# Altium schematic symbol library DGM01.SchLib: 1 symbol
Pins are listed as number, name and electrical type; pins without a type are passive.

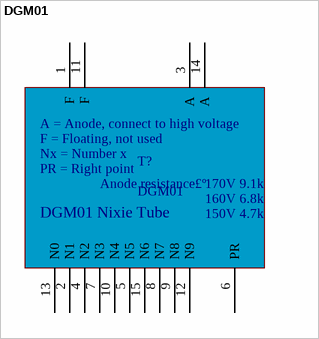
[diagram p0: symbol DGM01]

## DGM01
designator T?
inixielab.com
footprint DGM01 (DGM01 socket)
pins: 1 F, 2 N1, 3 A, 4 N2, 5 N5, 6 PR, 7 N3, 8 N7, 9 N8, 10 N4, 11 F, 12 N9, 13 N0, 14 A, 15 N6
